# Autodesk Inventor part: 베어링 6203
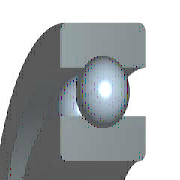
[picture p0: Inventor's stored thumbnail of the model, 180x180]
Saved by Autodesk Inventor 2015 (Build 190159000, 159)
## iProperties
IsCustomPart: 1
Created: 2015-09
Part Number: 베어링 6203
Material: 강철, 연강
Description: 깊은 그루브 볼 베어링
Document SubType Name: Modeling
Standard: KS B 2023
Standards Organization: KS
Language: ko-KR
Size Designation: 6203 - 17 x 40 x 12
Categories: <MemberInstance><Categories><Category DisplayName="샤프트 부품" InternalName="7f7aeb1f-a693-4053-b835-cee3144e0d98" Mnemonic="SHFT"><Category DisplayName="베어링" Inter
Density: 7.86 g/cm^3
Mass: 64.9809 g
Surface Area: 64.3582 cm^2
Volume: 8.26729 cm^3
Appearance: 강철
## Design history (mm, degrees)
sketch "스케치" dims "d0" = 5.98 (= -0.26 x WD + 0.26 x BD)
  geometry: L1 (3.01, 14.25)-(8.99, 14.25); L2 (6, 14.25)-(6, 11.26); L3 (6, 14.25)-(6, 17.24); L4 (3.778, 12.249)-(0, 12.249); L5 (0, 8.5)-(12, 8.5); L6 (3.778, 16.251)-(0, 16.251); L7 (0, 20)-(12, 20); L8 (12, 8.5)-(12, 12.249); L9 (8.222, 12.249)-(12, 12.249); L10 (8.222, 16.251)-(12, 16.251); L11 (12, 20)-(12, 16.251); L12 (-1.4, 0)-(8.4, 0) reference; L13 (0, -0.3)-(0, 5.3) reference
  constraints: 22 end point, 4 point on line, 2 collinear, 2 perpendicular, 2 symmetric about line, 1 midpoint, 1 parallel, 14 other
  dimensions: "d9" = 17 diameter of L5 L12 (= WD); "d11" = 40 diameter of L7 L12 (= BD); "d12" = 12 distance between parallel lines of L8 L13 (= KB); "d13" = 24.498 diameter of L9 L12 (= 0.326 x BD + 0.674 x WD)
revolve "본체" stored, may be unused: angle "d6" = 90 deg
revolve "볼" stored, may be unused: angle "d7" = 90 deg
pattern_circular "IDS_ARRAYBALL[SIMPL:T]" dims angle "d3" = 360 deg
body "Solid1"
fillet "모깎기1" dims "d1" = 0.6 (= KRS)
other parameters: "WD" = 17 [user parameter; used in 5 equation terms], "BD" = 40 [user parameter; used in 5 equation terms], "KB" = 12 [user parameter; used in 1 equation term], "KRS" = 0.6 [user parameter; used in 1 equation term], "d4" = 0, "d5" = 0, "d8" = 0, "d14" = 0, "d15" = 0, "BBA" = 0 [user parameter], "BC0" = 4750000 [user parameter], "BC" = 9560000 [user parameter], "WR" = 8.5 (= 0.5 x WD) [user parameter]
